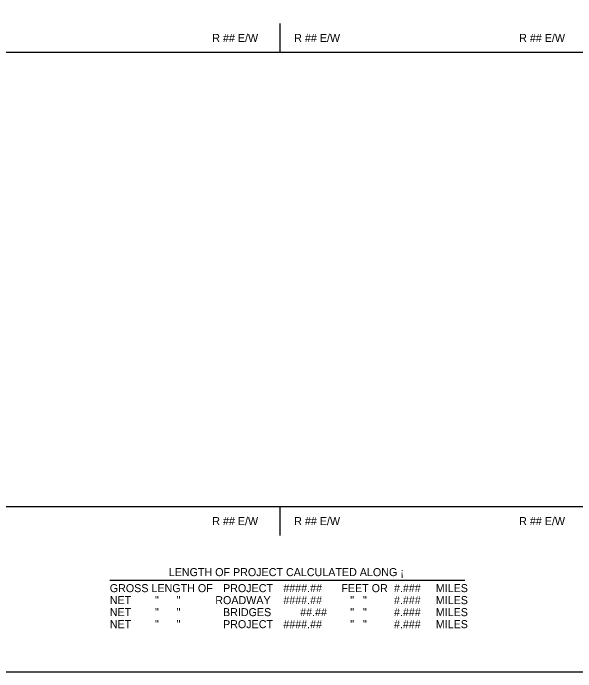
# Model space of a CAD drawing. Extents: x -819161 to 80911, y -6604 to 768454.
# Drawn here: x 79300 to 80136, y -5310 to -4331 of the extents above; entities that cross this region are included whole.
import ezdxf

# ---------------------------------------------------------------- set-up
doc = ezdxf.new("R2010")
doc.units = 0
for name, color, linetype in [('30', 7, 'Continuous'), ('SHET_Annotations', 7, 'Continuous'), ('SHET_Border-Lines', 7, 'Continuous'), ('SHET_Border-Text', 7, 'Continuous')]:
    doc.layers.add(name, color=color, linetype=linetype)

msp = doc.modelspace()

# ---------------------------------------------------------------- linework, layer by layer
at = {"layer": '30'}
msp.add_lwpolyline([(79157.1, -4389.25), (80257.21, -4389.25), (80257.21, -5064.78), (79157.1, -5064.78)], close=True, dxfattribs=at)
at = {"layer": 'SHET_Annotations'}
for p, q in [((79696.09, -4346.75), (79696.09, -4389.25)), ((79696.09, -5064.78), (79696.09, -5107.28))]:
    msp.add_line(p, q, dxfattribs=at)
at = {"layer": 'SHET_Border-Lines'}
msp.add_lwpolyline([(78502.99, -5310.09), (80911.32, -5310.09), (80911.32, -3751.75), (78502.99, -3751.75)], close=True, dxfattribs=at)
at = {"layer": 'SHET_Border-Text'}
msp.add_line((79443.66, -5173.8), (79970.66, -5173.8), dxfattribs=at)

# ---------------------------------------------------------------- texts
at = {"layer": 'SHET_Annotations'}
for s, p in [('R ## E/W', (79595.62, -4373.95)), ('R ## E/W', (79717.34, -4373.95)), ('R ## E/W', (80051.51, -4373.95)), ('R ## E/W', (79595.62, -5091.98)), ('R ## E/W', (79717.34, -5091.98)), ('R ## E/W', (80051.51, -5091.98)), ('####.##', (79701.13, -5191.65)), ('#.### ', (79865.51, -5191.65)), ('MILES', (79927.61, -5191.65)), ('####.##', (79701.13, -5209.5)), ('#.### ', (79865.51, -5209.5)), ('MILES', (79927.61, -5209.5)), ('##.##', (79726.17, -5227.35)), ('#.### ', (79865.51, -5227.35)), ('MILES', (79927.61, -5227.35)), ('####.##', (79701.13, -5245.2)), ('#.### ', (79865.51, -5245.2)), ('MILES', (79927.61, -5245.2))]:
    msp.add_text(s, height=11.9, dxfattribs=at).set_placement(p)
at = {"layer": 'SHET_Border-Text'}
for s, p in [('LENGTH OF PROJECT CALCULATED ALONG ¡', (79530.94, -5167.85)), ('GROSS LENGTH OF', (79443.35, -5191.65)), ('PROJECT', (79611.61, -5191.65)), ('FEET OR', (79787.3, -5191.65)), ('NET        "      "', (79443.35, -5209.5)), ('ROADWAY', (79600.08, -5209.5)), ('   "   "', (79787.3, -5209.5)), ('NET        "      "', (79443.35, -5227.35)), ('BRIDGES', (79611.55, -5227.35)), ('   "   "', (79787.3, -5227.35)), ('NET        "      "', (79443.35, -5245.2)), ('PROJECT', (79611.61, -5245.2)), ('   "   "', (79787.3, -5245.2))]:
    msp.add_text(s, height=11.9, dxfattribs=at).set_placement(p)

doc.saveas('drawing.dxf')
